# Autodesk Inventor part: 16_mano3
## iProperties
Created: 2002-11
Part Number: 16_mano3
Material: Par défaut
Document SubType Name: Modélisation
Designer: FIEVET
Control State: 0
Master: False
Checked Out: False
Shininess: 41.0
Length Units: 11269
Angle Units: 11279
Time Units: 11290
Mass Units: 11283
Length Display Precision: 3
Angle Display Precision: 2
Compacted: True
Density: 0.0
Volumn: 0.0
Area: 0.0
PropertySet Name: Model Information
Author: FIEVET
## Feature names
1. Extrusion1
2. Révolution1 [Revolution]
3. Extrusion2
4. Réseau circulaire1 [Circular Pattern]
5. Extrusion3
6. Réseau circulaire2 [Circular Pattern]
